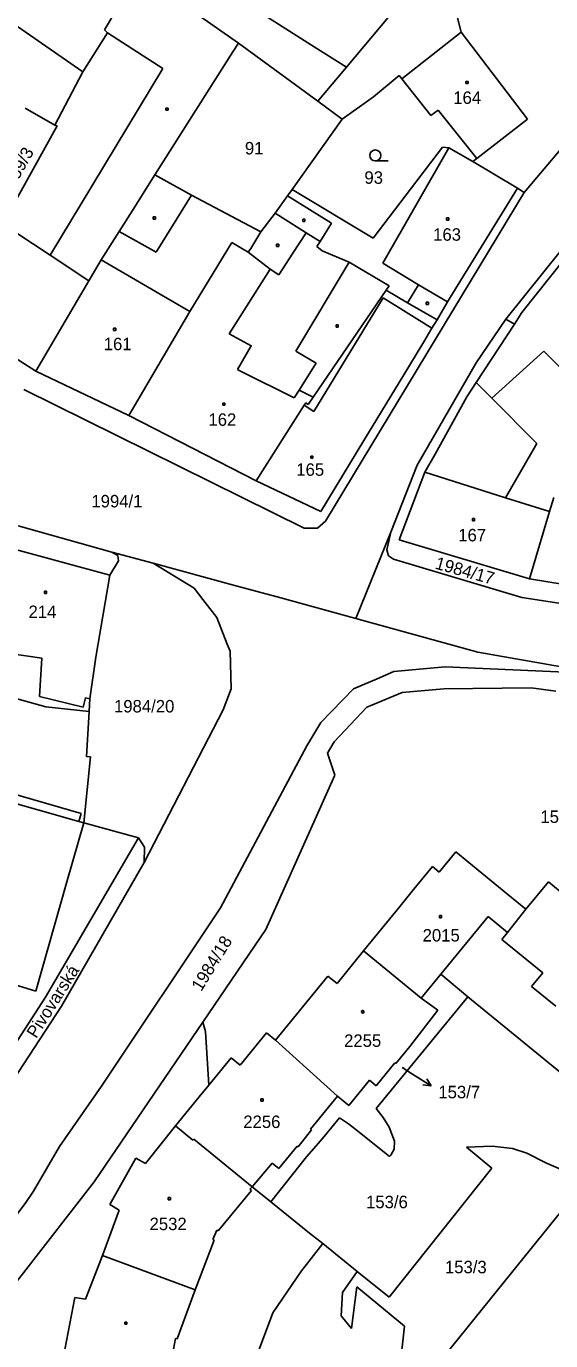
# Model space of a CAD drawing. Extents: x -795483 to -789093, y -1112258 to -1108741.
# Drawn here: x -791493.6 to -791422.1, y -1110756.8 to -1110577.6 of the extents above; entities that cross this region are included whole.
import ezdxf

# ---------------------------------------------------------------- set-up
doc = ezdxf.new("R2010")
doc.units = 0
for name, color, linetype in [('Komunikace', 7, 'Continuous'), ('Vrstva 1', 7, 'Continuous'), ('Vrstva 14', 7, 'Continuous'), ('Vrstva 15', 7, 'Continuous'), ('Vrstva 16', 7, 'Continuous'), ('Vrstva 2', 7, 'Continuous'), ('Vrstva 23', 7, 'Continuous'), ('Vrstva 25', 7, 'Continuous'), ('Vrstva 38', 7, 'Continuous')]:
    doc.layers.add(name, color=color, linetype=linetype)

msp = doc.modelspace()

# ---------------------------------------------------------------- linework, layer by layer
at = {"layer": 'Komunikace'}
msp.add_line((-791442.35, -1110719.53), (-791440.97, -1110720.4), dxfattribs=at)
at = {"layer": 'Vrstva 1'}
for p, q in [((-791436.99, -1110567.71), (-791449.96, -1110583.15)), ((-791434.35, -1110578.4), (-791436.99, -1110567.71)), ((-791478.34, -1110570.31), (-791482.92, -1110578.08)), ((-791454.7, -1110580.15), (-791469.51, -1110570.74)), ((-791497.95, -1110575.43), (-791485.88, -1110583.78)), ((-791482.51, -1110578.48), (-791485.88, -1110583.78)), ((-791482.92, -1110578.08), (-791482.51, -1110578.48)), ((-791434.35, -1110578.4), (-791425.3, -1110590.26)), ((-791465.43, -1110581.07), (-791464.68, -1110579.89)), ((-791464.68, -1110579.89), (-791453.85, -1110587.78)), ((-791449.96, -1110583.15), (-791454.7, -1110580.15)), ((-791476.04, -1110597.84), (-791465.43, -1110581.07)), ((-791409.57, -1110581.07), (-791425.75, -1110600.24)), ((-791485.88, -1110583.78), (-791489.68, -1110591.09)), ((-791453.85, -1110587.78), (-791449.96, -1110583.15)), ((-791442.78, -1110584.28), (-791446.27, -1110587.23)), ((-791442.41, -1110584.74), (-791442.78, -1110584.28)), ((-791438.46, -1110589.74), (-791442.41, -1110584.74)), ((-791446.27, -1110587.23), (-791450.52, -1110590.24)), ((-791489.68, -1110591.09), (-791493.73, -1110588.73)), ((-791450.52, -1110590.24), (-791453.85, -1110587.78)), ((-791437.45, -1110589.01), (-791438.46, -1110589.74)), ((-791432.18, -1110595.63), (-791437.45, -1110589.01)), ((-791489.36, -1110591.17), (-791496.13, -1110603.39)), ((-791489.68, -1110591.09), (-791489.36, -1110591.17)), ((-791457.37, -1110599.82), (-791450.52, -1110590.24)), ((-791432.18, -1110595.63), (-791425.3, -1110590.26)), ((-791436.89, -1110594.07), (-791446.32, -1110606.46)), ((-791436.01, -1110594.16), (-791436.89, -1110594.07)), ((-791432.73, -1110596), (-791436.01, -1110594.16)), ((-791432.73, -1110596), (-791432.18, -1110595.63)), ((-791426.68, -1110599.66), (-791432.73, -1110596)), ((-791410.29, -1110595.06), (-791428.27, -1110617.52)), ((-791409.54, -1110595.73), (-791426.07, -1110616.61)), ((-791476.04, -1110597.84), (-791479.12, -1110602.71)), ((-791471.08, -1110600.6), (-791476.04, -1110597.84)), ((-791457.37, -1110599.82), (-791458.01, -1110600.72)), ((-791446.32, -1110606.46), (-791457.37, -1110599.82)), ((-791436.19, -1110615.16), (-791426.68, -1110599.66)), ((-791425.75, -1110600.24), (-791432.95, -1110612.2)), ((-791425.75, -1110600.24), (-791426.68, -1110599.66)), ((-791461.61, -1110605.59), (-791471.08, -1110600.6)), ((-791458.01, -1110600.72), (-791459.68, -1110603.06)), ((-791479.12, -1110602.71), (-791480.91, -1110605.55)), ((-791459.68, -1110603.06), (-791461.61, -1110605.59)), ((-791459.68, -1110603.06), (-791455.43, -1110605.73)), ((-791480.91, -1110605.55), (-791483.38, -1110609.44)), ((-791461.61, -1110605.59), (-791462.99, -1110607.87)), ((-791465.56, -1110607.07), (-791471.31, -1110616.49)), ((-791463.36, -1110608.4), (-791465.56, -1110607.07)), ((-791455.43, -1110605.73), (-791453.54, -1110606.92)), ((-791453.54, -1110606.92), (-791453.98, -1110607.63)), ((-791462.99, -1110607.87), (-791463.36, -1110608.4)), ((-791453.98, -1110607.63), (-791453.28, -1110608.21)), ((-791453.28, -1110608.21), (-791449.58, -1110609.73)), ((-791483.38, -1110609.44), (-791485.05, -1110612.29)), ((-791449.58, -1110609.73), (-791444.16, -1110612.96)), ((-791485.05, -1110612.29), (-791492.25, -1110624.62)), ((-791432.95, -1110612.2), (-791452.82, -1110645.03)), ((-791444.57, -1110613.56), (-791454.47, -1110628.13)), ((-791444.16, -1110612.96), (-791444.57, -1110613.56)), ((-791441.63, -1110615.28), (-791444.57, -1110613.56)), ((-791437.61, -1110617.6), (-791441.63, -1110615.28)), ((-791437.61, -1110617.6), (-791436.19, -1110615.16)), ((-791492.25, -1110624.62), (-791505.03, -1110616.46)), ((-791471.31, -1110616.49), (-791479.59, -1110630.66)), ((-791438.32, -1110618.76), (-791437.61, -1110617.6)), ((-791427.09, -1110618.18), (-791432.29, -1110626.14)), ((-791428.27, -1110617.52), (-791432.27, -1110623.48)), ((-791427.09, -1110618.18), (-791428.27, -1110617.52)), ((-791426.07, -1110616.61), (-791427.09, -1110618.18)), ((-791439.44, -1110620.6), (-791438.32, -1110618.76)), ((-791442.15, -1110625.08), (-791439.44, -1110620.6)), ((-791432.27, -1110623.48), (-791440.31, -1110637.4)), ((-791423.09, -1110621.89), (-791430.14, -1110628.3)), ((-791423.09, -1110621.89), (-791413.68, -1110631.22)), ((-791479.59, -1110630.66), (-791492.25, -1110624.62)), ((-791447.58, -1110634.05), (-791442.15, -1110625.08)), ((-791455.72, -1110646.01), (-791493.89, -1110627.11)), ((-791432.29, -1110626.14), (-791433.57, -1110628.09)), ((-791431.93, -1110626.5), (-791432.29, -1110626.14)), ((-791430.14, -1110628.3), (-791431.93, -1110626.5)), ((-791455.49, -1110628.91), (-791455.7, -1110629.25)), ((-791455.16, -1110629.14), (-791455.49, -1110628.91)), ((-791454.47, -1110628.13), (-791455.16, -1110629.14)), ((-791433.57, -1110628.09), (-791437.86, -1110635.92)), ((-791462.25, -1110639.56), (-791479.59, -1110630.66)), ((-791455.7, -1110629.25), (-791462.25, -1110639.56)), ((-791453.45, -1110643.75), (-791447.58, -1110634.05)), ((-791437.86, -1110635.92), (-791439.29, -1110638.38)), ((-791440.31, -1110637.4), (-791443.92, -1110646.53)), ((-791453.45, -1110643.75), (-791462.25, -1110639.56)), ((-791439.29, -1110638.38), (-791442.79, -1110647.61)), ((-791421.7, -1110641.8), (-791422.28, -1110643.74)), ((-791453.88, -1110645.99), (-791452.82, -1110645.03)), ((-791422.28, -1110643.74), (-791425.03, -1110652.89)), ((-791481.93, -1110649.27), (-791494.68, -1110645.68)), ((-791455.72, -1110646.01), (-791453.88, -1110645.99)), ((-791448.69, -1110658.31), (-791443.92, -1110646.53)), ((-791443.92, -1110646.53), (-791444.46, -1110648.94)), ((-791442.79, -1110647.61), (-791425.03, -1110652.89)), ((-791495.54, -1110648.77), (-791482.21, -1110652.4)), ((-791476.29, -1110650.78), (-791481.93, -1110649.27)), ((-791481.12, -1110649.74), (-791481.93, -1110649.27)), ((-791481.01, -1110650.47), (-791481.12, -1110649.74)), ((-791444.46, -1110648.94), (-791444.24, -1110649.78)), ((-791444.24, -1110649.78), (-791443.57, -1110650.23)), ((-791426.06, -1110655.45), (-791443.57, -1110650.23)), ((-791481.01, -1110650.47), (-791482.21, -1110652.4)), ((-791476.29, -1110650.78), (-791470.69, -1110654.17)), ((-791465.35, -1110653.77), (-791476.29, -1110650.78)), ((-791482.21, -1110652.4), (-791484.09, -1110663.58)), ((-791458.89, -1110655.51), (-791465.35, -1110653.77)), ((-791425.03, -1110652.89), (-791402.31, -1110656.68)), ((-791469.51, -1110655.7), (-791470.69, -1110654.17)), ((-791467.62, -1110658.16), (-791469.51, -1110655.7)), ((-791448.69, -1110658.31), (-791458.89, -1110655.51)), ((-791403.39, -1110658.99), (-791426.06, -1110655.45)), ((-791466.19, -1110661.79), (-791467.62, -1110658.16)), ((-791432.05, -1110662.91), (-791448.69, -1110658.31)), ((-791465.8, -1110662.78), (-791466.19, -1110661.79)), ((-791465.66, -1110667.91), (-791465.8, -1110662.78)), ((-791415.41, -1110665.84), (-791432.05, -1110662.91)), ((-791484.09, -1110663.58), (-791484.91, -1110669.26)), ((-791445.79, -1110666.52), (-791448.98, -1110667.92)), ((-791443.5, -1110665.52), (-791445.79, -1110666.52)), ((-791443.5, -1110665.52), (-791437.02, -1110664.95)), ((-791436.52, -1110664.91), (-791437.02, -1110664.95)), ((-791415.41, -1110665.84), (-791436.52, -1110664.91)), ((-791466.75, -1110670.75), (-791465.66, -1110667.91)), ((-791448.98, -1110667.92), (-791453.46, -1110672.49)), ((-791442.39, -1110668.4), (-791436.69, -1110667.92)), ((-791436.69, -1110667.92), (-791424.8, -1110667.76)), ((-791424.8, -1110667.76), (-791421.44, -1110668.2)), ((-791497.3, -1110668.56), (-791490.93, -1110670.34)), ((-791484.91, -1110669.26), (-791485.01, -1110671.01)), ((-791446.75, -1110670.23), (-791442.39, -1110668.4)), ((-791490.93, -1110670.34), (-791485.01, -1110671.01)), ((-791485.36, -1110677.11), (-791485.01, -1110671.01)), ((-791477.52, -1110691.57), (-791466.75, -1110670.75)), ((-791451.61, -1110675.14), (-791447.19, -1110670.41)), ((-791447.19, -1110670.41), (-791446.75, -1110670.23)), ((-791453.46, -1110672.49), (-791455.34, -1110675.65)), ((-791452.52, -1110676.65), (-791451.61, -1110675.14)), ((-791484.82, -1110677.19), (-791485.74, -1110686.17)), ((-791485.36, -1110677.11), (-791484.82, -1110677.19)), ((-791455.34, -1110675.65), (-791467.12, -1110697.76)), ((-791451.56, -1110679.67), (-791452.52, -1110676.65)), ((-791486.09, -1110684.87), (-791502.83, -1110680.1)), ((-791460.94, -1110700.71), (-791451.56, -1110679.67)), ((-791485.74, -1110686.17), (-791488.04, -1110694.22)), ((-791486.41, -1110685.98), (-791486.09, -1110684.87)), ((-791485.74, -1110686.17), (-791486.41, -1110685.98)), ((-791478.27, -1110688.19), (-791485.74, -1110686.17)), ((-791478.27, -1110688.19), (-791490.95, -1110709.91)), ((-791477.48, -1110689.46), (-791478.27, -1110688.19)), ((-791477.52, -1110691.57), (-791477.48, -1110689.46)), ((-791488.78, -1110711.13), (-791477.52, -1110691.57)), ((-791437.31, -1110692.9), (-791435.04, -1110690.11)), ((-791435.04, -1110690.11), (-791427.97, -1110695.94)), ((-791440.99, -1110695.47), (-791438.26, -1110692.13)), ((-791438.26, -1110692.13), (-791437.31, -1110692.9)), ((-791488.04, -1110694.22), (-791492.28, -1110709.09)), ((-791422.44, -1110694.21), (-791425.52, -1110697.95)), ((-791419.66, -1110696.5), (-791422.44, -1110694.21)), ((-791442.64, -1110697.5), (-791440.99, -1110695.47)), ((-791427.97, -1110695.94), (-791425.52, -1110697.95)), ((-791447.65, -1110703.62), (-791442.64, -1110697.5)), ((-791425.52, -1110697.95), (-791428.01, -1110701.09)), ((-791437.12, -1110706.81), (-791430.66, -1110698.93)), ((-791430.66, -1110698.93), (-791428.01, -1110701.09)), ((-791469.52, -1110713.32), (-791460.94, -1110700.71)), ((-791428.01, -1110701.09), (-791428.81, -1110702.07)), ((-791428.81, -1110702.07), (-791423.22, -1110706.61)), ((-791509.53, -1110703.89), (-791492.28, -1110709.09)), ((-791447.65, -1110703.62), (-791451.24, -1110708.06)), ((-791439.78, -1110710.06), (-791447.65, -1110703.62)), ((-791452.48, -1110707.05), (-791459.61, -1110715.79)), ((-791451.24, -1110708.06), (-791452.48, -1110707.05)), ((-791437.12, -1110706.81), (-791439.78, -1110710.06)), ((-791433.41, -1110709.86), (-791437.12, -1110706.81)), ((-791423.22, -1110706.61), (-791424.75, -1110708.48)), ((-791424.75, -1110708.48), (-791421.44, -1110711.17)), ((-791490.95, -1110709.91), (-791501.12, -1110725.63)), ((-791499.08, -1110726.91), (-791488.78, -1110711.13)), ((-791445.89, -1110725.1), (-791433.41, -1110709.86)), ((-791439.78, -1110710.06), (-791437.52, -1110711.7)), ((-791418.56, -1110722.03), (-791433.41, -1110709.86)), ((-791441.34, -1110716.64), (-791437.52, -1110711.7)), ((-791469.52, -1110713.32), (-791484.32, -1110735.08)), ((-791469.52, -1110713.32), (-791469.15, -1110714.61)), ((-791468.7, -1110721.93), (-791469.15, -1110714.61)), ((-791464.42, -1110719.19), (-791460.84, -1110714.79)), ((-791459.61, -1110715.79), (-791460.84, -1110714.79)), ((-791459.61, -1110715.79), (-791451.19, -1110723.41)), ((-791443.25, -1110718.98), (-791441.34, -1110716.64)), ((-791468.7, -1110721.93), (-791465.65, -1110718.19)), ((-791465.65, -1110718.19), (-791464.42, -1110719.19)), ((-791445.89, -1110721.99), (-791443.37, -1110718.89)), ((-791443.37, -1110718.89), (-791443.25, -1110718.98)), ((-791470.01, -1110723.53), (-791468.7, -1110721.93)), ((-791449.63, -1110724.68), (-791446.82, -1110721.23)), ((-791446.82, -1110721.23), (-791445.89, -1110721.99)), ((-791473.23, -1110727.47), (-791470.01, -1110723.53)), ((-791451.19, -1110723.41), (-791454.85, -1110727.9)), ((-791451.19, -1110723.41), (-791449.63, -1110724.68)), ((-791444.94, -1110726.34), (-791445.89, -1110725.1)), ((-791473.23, -1110727.47), (-791477.33, -1110732.59)), ((-791473.23, -1110727.47), (-791470.87, -1110729.4)), ((-791450.89, -1110726.38), (-791453, -1110728.91)), ((-791450.89, -1110726.38), (-791449.68, -1110727.19)), ((-791449.68, -1110727.19), (-791448.46, -1110728.16)), ((-791444.13, -1110727.63), (-791444.94, -1110726.34)), ((-791470.87, -1110729.4), (-791470.77, -1110729.28)), ((-791462.79, -1110735.8), (-791470.77, -1110729.28)), ((-791454.73, -1110728), (-791456.54, -1110730.33)), ((-791454.85, -1110727.9), (-791454.73, -1110728)), ((-791454.1, -1110730.19), (-791453, -1110728.91)), ((-791444.09, -1110731.64), (-791448.46, -1110728.16)), ((-791443.42, -1110729.55), (-791444.13, -1110727.63)), ((-791456.65, -1110730.23), (-791459.19, -1110733.29)), ((-791456.54, -1110730.33), (-791456.65, -1110730.23)), ((-791455.4, -1110731.7), (-791454.1, -1110730.19)), ((-791443.93, -1110731.44), (-791443.47, -1110730.65)), ((-791443.47, -1110730.65), (-791443.42, -1110729.55)), ((-791433.59, -1110730.37), (-791430.1, -1110730.24)), ((-791430.15, -1110733.22), (-791433.59, -1110730.37)), ((-791430.1, -1110730.24), (-791427.35, -1110730.56)), ((-791427.35, -1110730.56), (-791425.37, -1110731.18)), ((-791478.65, -1110731.85), (-791482.19, -1110738.19)), ((-791477.33, -1110732.59), (-791478.65, -1110731.85)), ((-791460.09, -1110732.54), (-791462.79, -1110735.8)), ((-791460.27, -1110737.8), (-791455.4, -1110731.7)), ((-791459.19, -1110733.29), (-791460.09, -1110732.54)), ((-791444.09, -1110731.64), (-791443.93, -1110731.44)), ((-791425.37, -1110731.18), (-791422.73, -1110732.55)), ((-791422.73, -1110732.55), (-791420.17, -1110733.66)), ((-791444.14, -1110750.83), (-791430.15, -1110733.22)), ((-791428.43, -1110748.66), (-791416.76, -1110734.21)), ((-791484.32, -1110735.08), (-791500.47, -1110755.89)), ((-791467.42, -1110741.77), (-791462.87, -1110736.3)), ((-791463.11, -1110736.1), (-791462.79, -1110735.8)), ((-791462.87, -1110736.3), (-791463.11, -1110736.1)), ((-791462.79, -1110735.8), (-791460.27, -1110737.8)), ((-791482.19, -1110738.19), (-791480.93, -1110738.94)), ((-791460.27, -1110737.8), (-791454.97, -1110742.08)), ((-791480.93, -1110738.94), (-791483.17, -1110745.13)), ((-791468.17, -1110742.97), (-791467.62, -1110741.68)), ((-791467.62, -1110741.68), (-791467.42, -1110741.77)), ((-791470.56, -1110749.82), (-791467.99, -1110743.07)), ((-791467.99, -1110743.07), (-791468.17, -1110742.97)), ((-791453.16, -1110743.48), (-791455.41, -1110746.37)), ((-791453.16, -1110743.48), (-791454.97, -1110742.08)), ((-791448.49, -1110747.34), (-791453.16, -1110743.48)), ((-791485.5, -1110751.11), (-791483.17, -1110745.13)), ((-791483.17, -1110745.13), (-791470.56, -1110749.82)), ((-791456.06, -1110747.21), (-791459.97, -1110752.95)), ((-791455.41, -1110746.37), (-791456.06, -1110747.21)), ((-791450.48, -1110750.19), (-791448.49, -1110747.34)), ((-791444.14, -1110750.83), (-791448.49, -1110747.34)), ((-791437.75, -1110760.21), (-791428.43, -1110748.66)), ((-791470.56, -1110749.82), (-791473.01, -1110756.51)), ((-791450.68, -1110753.37), (-791450.48, -1110750.19)), ((-791448.54, -1110749.43), (-791449.28, -1110755.11)), ((-791442.04, -1110754.77), (-791448.54, -1110749.43)), ((-791488.32, -1110757.96), (-791486.94, -1110750.87)), ((-791486.94, -1110750.87), (-791485.5, -1110751.11)), ((-791459.97, -1110752.95), (-791462.76, -1110760.34)), ((-791449.28, -1110755.11), (-791450.68, -1110753.37)), ((-791442.7, -1110760.47), (-791442.04, -1110754.77)), ((-791473.24, -1110756.43), (-791473.51, -1110757.9)), ((-791473.01, -1110756.51), (-791473.24, -1110756.43))]:
    msp.add_line(p, q, dxfattribs=at)
msp.add_lwpolyline([(-791507.95, -1110756.65), (-791502.11, -1110749.2), (-791493.72, -1110738.06), (-791492.6, -1110736.36), (-791489.06, -1110730.3), (-791483.34, -1110722.06), (-791467.12, -1110697.76)], dxfattribs=at)
at = {"layer": 'Vrstva 16'}
for p, q in [((-791440.97, -1110720.4), (-791438.44, -1110722.01)), ((-791438.44, -1110722.01), (-791439.55, -1110721.89)), ((-791438.44, -1110722.01), (-791439.01, -1110721.05))]:
    msp.add_line(p, q, dxfattribs=at)
at = {"layer": 'Vrstva 2'}
for p, q in [((-791478.34, -1110570.31), (-791464.68, -1110579.89)), ((-791482.51, -1110578.48), (-791474.96, -1110583.33)), ((-791434.35, -1110578.4), (-791442.41, -1110584.74)), ((-791474.96, -1110583.33), (-791484.64, -1110599.39)), ((-791436.01, -1110594.16), (-791444.99, -1110609.89)), ((-791484.64, -1110599.39), (-791490.32, -1110608.81)), ((-791471.08, -1110600.6), (-791475.9, -1110608.4)), ((-791452, -1110604.44), (-791458.01, -1110600.72)), ((-791497.33, -1110604.18), (-791490.32, -1110608.81)), ((-791475.9, -1110608.4), (-791480.91, -1110605.55)), ((-791453.54, -1110606.92), (-791452, -1110604.44)), ((-791457.24, -1110608.5), (-791455.43, -1110605.73)), ((-791490.32, -1110608.81), (-791485.05, -1110612.29)), ((-791460.33, -1110610.7), (-791463.36, -1110608.4)), ((-791459.18, -1110611.47), (-791457.24, -1110608.5)), ((-791483.38, -1110609.44), (-791471.31, -1110616.49)), ((-791465.93, -1110619.49), (-791460.33, -1110610.7)), ((-791460.33, -1110610.7), (-791459.18, -1110611.47)), ((-791449.58, -1110609.73), (-791456.87, -1110621.87)), ((-791444.99, -1110609.89), (-791440.16, -1110612.82)), ((-791440.16, -1110612.82), (-791441.63, -1110615.28)), ((-791440.16, -1110612.82), (-791436.19, -1110615.16)), ((-791444.95, -1110614.62), (-791454.42, -1110630.12)), ((-791438.32, -1110618.76), (-791444.95, -1110614.62)), ((-791456.87, -1110621.87), (-791454.07, -1110623.49)), ((-791454.07, -1110623.49), (-791454.25, -1110623.78)), ((-791464.82, -1110624.37), (-791464.37, -1110624.59)), ((-791457.08, -1110628.23), (-791464.37, -1110624.59)), ((-791454.25, -1110623.78), (-791456.41, -1110627.18)), ((-791456.41, -1110627.18), (-791457.08, -1110628.23)), ((-791454.47, -1110628.13), (-791456.41, -1110627.18)), ((-791430.14, -1110628.3), (-791424.03, -1110634.45)), ((-791454.42, -1110630.12), (-791455.7, -1110629.25)), ((-791424.03, -1110634.45), (-791428.29, -1110641.85)), ((-791439.29, -1110638.38), (-791428.29, -1110641.85)), ((-791422.28, -1110643.74), (-791428.29, -1110641.85)), ((-791496.13, -1110663.02), (-791491.43, -1110663.73)), ((-791491.43, -1110663.73), (-791491.77, -1110668.94)), ((-791491.77, -1110668.94), (-791485.8, -1110670.39)), ((-791485.8, -1110670.39), (-791485.49, -1110669.12)), ((-791485.49, -1110669.12), (-791484.91, -1110669.26)), ((-791503.15, -1110681.2), (-791486.41, -1110685.98))]:
    msp.add_line(p, q, dxfattribs=at)
msp.add_lwpolyline([(-791465.93, -1110619.49), (-791462.92, -1110621.14), (-791464.82, -1110624.37)], dxfattribs=at)
at = {"layer": 'Vrstva 23'}
msp.add_line((-791446.03, -1110595.95), (-791444.28, -1110595.95), dxfattribs=at)
msp.add_circle((-791446.03, -1110595.2), 0.75, dxfattribs=at)
at = {"layer": 'Vrstva 25'}
for p, q in [((-791433.69, -1110585.1), (-791433.39, -1110585.1)), ((-791433.69, -1110585.4), (-791433.69, -1110585.1)), ((-791433.39, -1110585.4), (-791433.69, -1110585.4)), ((-791433.39, -1110585.1), (-791433.39, -1110585.4)), ((-791474.54, -1110588.74), (-791474.24, -1110588.74)), ((-791474.54, -1110589.04), (-791474.54, -1110588.74)), ((-791474.24, -1110589.04), (-791474.54, -1110589.04)), ((-791474.24, -1110588.74), (-791474.24, -1110589.04)), ((-791476.28, -1110603.57), (-791475.98, -1110603.57)), ((-791476.28, -1110603.87), (-791476.28, -1110603.57)), ((-791475.98, -1110603.87), (-791476.28, -1110603.87)), ((-791475.98, -1110603.57), (-791475.98, -1110603.87)), ((-791455.91, -1110603.88), (-791455.61, -1110603.88)), ((-791455.91, -1110604.18), (-791455.91, -1110603.88)), ((-791455.61, -1110603.88), (-791455.61, -1110604.18)), ((-791436.33, -1110603.72), (-791436.03, -1110603.72)), ((-791436.33, -1110604.02), (-791436.33, -1110603.72)), ((-791436.03, -1110603.72), (-791436.03, -1110604.02)), ((-791455.61, -1110604.18), (-791455.91, -1110604.18)), ((-791436.03, -1110604.02), (-791436.33, -1110604.02)), ((-791459.48, -1110607.29), (-791459.18, -1110607.29)), ((-791459.48, -1110607.59), (-791459.48, -1110607.29)), ((-791459.18, -1110607.29), (-791459.18, -1110607.59)), ((-791459.18, -1110607.59), (-791459.48, -1110607.59)), ((-791439.09, -1110615.21), (-791438.79, -1110615.21)), ((-791439.09, -1110615.51), (-791439.09, -1110615.21)), ((-791438.79, -1110615.51), (-791439.09, -1110615.51)), ((-791438.79, -1110615.21), (-791438.79, -1110615.51)), ((-791481.68, -1110618.75), (-791481.38, -1110618.75)), ((-791481.68, -1110619.05), (-791481.68, -1110618.75)), ((-791481.38, -1110619.05), (-791481.68, -1110619.05)), ((-791481.38, -1110618.75), (-791481.38, -1110619.05)), ((-791451.38, -1110618.28), (-791451.08, -1110618.28)), ((-791451.38, -1110618.58), (-791451.38, -1110618.28)), ((-791451.08, -1110618.58), (-791451.38, -1110618.58)), ((-791451.08, -1110618.28), (-791451.08, -1110618.58)), ((-791466.81, -1110628.95), (-791466.51, -1110628.95)), ((-791466.81, -1110629.25), (-791466.81, -1110628.95)), ((-791466.51, -1110628.95), (-791466.51, -1110629.25)), ((-791466.51, -1110629.25), (-791466.81, -1110629.25)), ((-791454.82, -1110636.17), (-791454.52, -1110636.17)), ((-791454.82, -1110636.47), (-791454.82, -1110636.17)), ((-791454.52, -1110636.47), (-791454.82, -1110636.47)), ((-791454.52, -1110636.17), (-791454.52, -1110636.47)), ((-791432.8, -1110644.7), (-791432.5, -1110644.7)), ((-791432.8, -1110645), (-791432.8, -1110644.7)), ((-791432.5, -1110645), (-791432.8, -1110645)), ((-791432.5, -1110644.7), (-791432.5, -1110645)), ((-791491.1, -1110654.6), (-791490.8, -1110654.6)), ((-791491.1, -1110654.9), (-791491.1, -1110654.6)), ((-791490.8, -1110654.9), (-791491.1, -1110654.9)), ((-791490.8, -1110654.6), (-791490.8, -1110654.9)), ((-791437.3, -1110698.79), (-791437, -1110698.79)), ((-791437.3, -1110699.09), (-791437.3, -1110698.79)), ((-791437, -1110698.79), (-791437, -1110699.09)), ((-791437, -1110699.09), (-791437.3, -1110699.09)), ((-791447.95, -1110711.9), (-791447.73, -1110711.7)), ((-791447.75, -1110712.13), (-791447.95, -1110711.9)), ((-791447.53, -1110711.93), (-791447.75, -1110712.13)), ((-791447.73, -1110711.7), (-791447.53, -1110711.93)), ((-791461.61, -1110723.79), (-791461.31, -1110723.79)), ((-791461.61, -1110724.09), (-791461.61, -1110723.79)), ((-791461.31, -1110723.79), (-791461.31, -1110724.09)), ((-791461.31, -1110724.09), (-791461.61, -1110724.09)), ((-791474.24, -1110737.24), (-791473.94, -1110737.24)), ((-791474.24, -1110737.54), (-791474.24, -1110737.24)), ((-791473.94, -1110737.54), (-791474.24, -1110737.54)), ((-791473.94, -1110737.24), (-791473.94, -1110737.54)), ((-791480.16, -1110754.21), (-791479.86, -1110754.21)), ((-791480.16, -1110754.51), (-791480.16, -1110754.21)), ((-791479.86, -1110754.21), (-791479.86, -1110754.51)), ((-791479.86, -1110754.51), (-791480.16, -1110754.51))]:
    msp.add_line(p, q, dxfattribs=at)

# ---------------------------------------------------------------- texts
at = {"layer": 'Vrstva 14'}
for s, height, p in [('91', 1.7, (-791463.79, -1110595.06)), ('93', 1.7, (-791447.51, -1110599.06)), ('1994/1', 1.7, (-791484.7, -1110643.17)), ('1984/20', 1.7, (-791481.62, -1110671.12)), ('153/1', 1.7, (-791423.54, -1110686.18)), ('153/7', 0.1, (-791442.35, -1110719.53)), ('153/6', 1.7, (-791447.29, -1110738.69)), ('153/3', 1.7, (-791436.54, -1110747.56))]:
    msp.add_text(s, height=height, dxfattribs=at).set_placement(p)
for s, rotation, p in [('1984/17', 344.3382, (-791438, -1110651.5)), ('1984/18', 58.4857, (-791469.74, -1110709.25))]:
    msp.add_text(s, height=1.7, rotation=rotation, dxfattribs=at).set_placement(p)
at = {"layer": 'Vrstva 15'}
for s, p in [('164', (-791435.41, -1110588.17)), ('163', (-791438.15, -1110606.82)), ('161', (-791483.02, -1110621.74)), ('162', (-791468.76, -1110632.05)), ('165', (-791456.79, -1110638.86)), ('167', (-791434.73, -1110647.8)), ('214', (-791493.27, -1110658.25)), ('2015', (-791439.58, -1110702.34)), ('2255', (-791450.28, -1110716.7)), ('2256', (-791464.01, -1110727.76)), ('2532', (-791476.78, -1110741.68))]:
    msp.add_text(s, height=1.7, dxfattribs=at).set_placement(p)
msp.add_text('159/3', height=1.7, rotation=60.9183, dxfattribs=at).set_placement((-791495.24, -1110599.67))
at = {"layer": 'Vrstva 16'}
msp.add_text('153/7', height=1.7, dxfattribs=at).set_placement((-791437.44, -1110723.71))
at = {"layer": 'Vrstva 38'}
msp.add_text('Pivovarská', height=1.7, rotation=57.7957, dxfattribs=at).set_placement((-791492.21, -1110715.65))

doc.saveas('drawing.dxf')
